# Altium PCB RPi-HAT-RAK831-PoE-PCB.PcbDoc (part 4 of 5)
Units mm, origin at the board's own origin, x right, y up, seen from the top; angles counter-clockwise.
Board outline 65 x 56 mm, 2 copper layers (Top Layer, Bottom Layer); 9 components, 14 nets, 9110 pads, 249 vias.
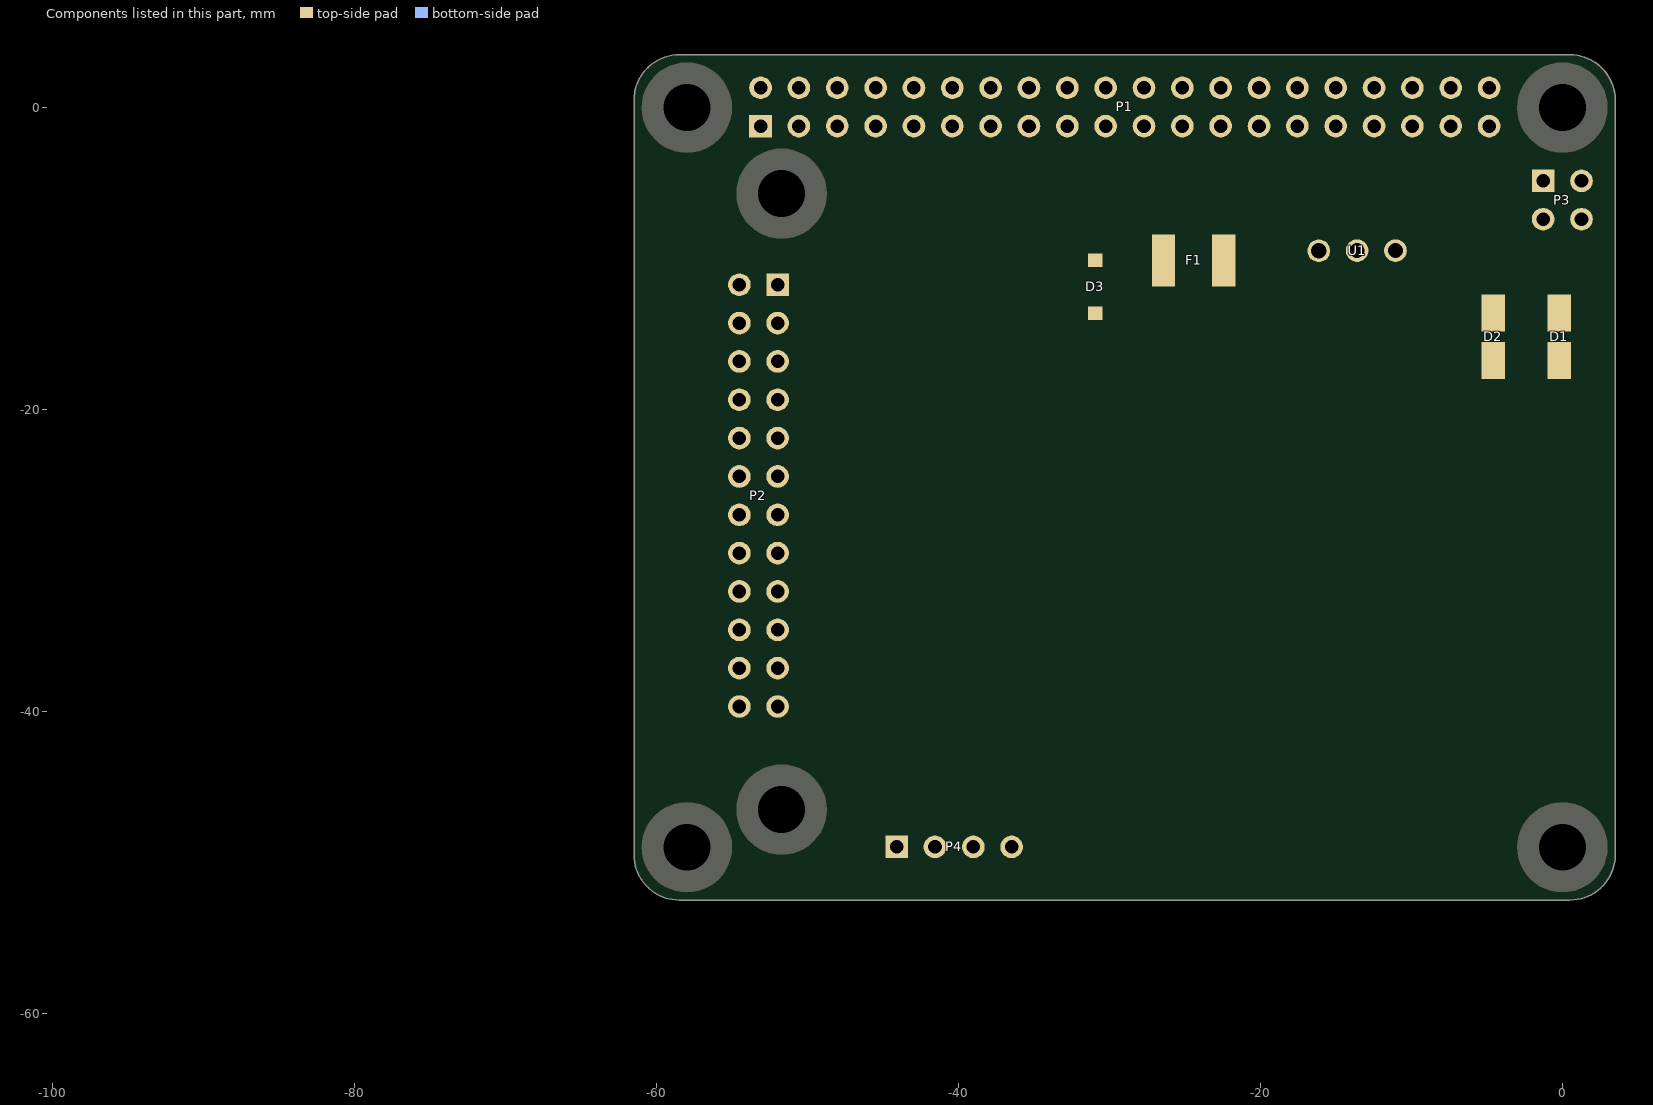
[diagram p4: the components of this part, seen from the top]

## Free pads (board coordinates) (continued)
  round 0.025 on Top Overlay: 1(-34.555,-45.483) 1(-34.555,-45.457) 1(-34.555,-45.432) 1(-34.555,-45.407) 1(-34.555,-45.381) 1(-34.555,-45.356) 1(-34.555,-45.33) 1(-34.555,-45.305) 1(-34.555,-45.28) 1(-34.555,-45.254) 1(-34.555,-45.229) 1(-34.555,-45.203) 1(-34.555,-45.178) 1(-34.555,-45.153) 1(-34.555,-45.127) 1(-34.555,-45.102) 1(-34.555,-45.076) 1(-34.555,-45.051) 1(-34.555,-45.026) 1(-34.555,-45) 1(-34.555,-44.975) 1(-34.555,-44.949) 1(-34.555,-44.924) 1(-34.555,-44.899) 1(-34.555,-44.873) 1(-34.555,-44.848) 1(-34.555,-44.822) 1(-34.555,-44.797) 1(-34.555,-44.772) 1(-34.555,-44.746) 1(-34.555,-44.721) 1(-34.555,-44.695) 1(-34.555,-44.67) 1(-34.555,-44.645) 1(-34.555,-44.619) 1(-34.555,-44.594) 1(-34.555,-44.568) 1(-34.555,-44.543) 1(-34.555,-44.518) 1(-34.555,-44.492) 1(-34.555,-44.467) 1(-34.555,-44.441) 1(-34.555,-44.416) 1(-34.555,-44.391) 1(-34.555,-44.365) 1(-34.555,-44.34) 1(-34.555,-44.314) 1(-34.555,-44.289) 1(-34.555,-44.264) 1(-34.555,-44.238) 1(-34.555,-44.213) 1(-34.555,-44.187) 1(-34.555,-44.162) 1(-34.555,-44.137) 1(-34.555,-44.111) 1(-34.555,-44.086) 1(-34.555,-44.06) 1(-34.555,-44.035) 1(-34.555,-44.01) 1(-34.555,-43.984) 1(-34.555,-43.959) 1(-34.555,-43.933) 1(-34.555,-43.908) 1(-34.555,-43.883) 1(-34.555,-43.857) 1(-34.555,-43.832) 1(-34.555,-43.806) 1(-34.555,-43.781) 1(-34.555,-43.756) 1(-34.555,-43.73) 1(-34.555,-43.705) 1(-34.555,-43.679) 1(-34.555,-43.654) 1(-34.555,-43.629) 1(-34.555,-43.603) 1(-34.555,-43.578) 1(-34.555,-43.552) 1(-34.555,-43.527) 1(-34.555,-43.502) 1(-34.555,-43.476) 1(-34.555,-43.451) 1(-34.555,-43.425) 1(-34.555,-43.4) 1(-34.555,-43.375) 1(-34.555,-43.349) 1(-34.555,-43.324) 1(-34.555,-43.298) 1(-34.555,-43.273) 1(-34.555,-43.248) 1(-34.555,-43.222) 1(-34.555,-43.197) 1(-34.555,-43.171) 1(-34.555,-43.146) 1(-34.53,-43.121) 1(-33.971,-44.975) 1(-33.971,-44.949) 1(-33.971,-44.924) 1(-33.971,-44.899) 1(-33.971,-44.873) 1(-33.971,-44.848) 1(-33.971,-44.822) 1(-33.971,-44.797) 1(-33.971,-44.772) 1(-33.971,-44.746) 1(-33.971,-44.721) 1(-33.971,-44.695) 1(-33.971,-44.67) 1(-33.971,-44.645) 1(-33.971,-44.619) 1(-33.971,-44.594) 1(-33.971,-44.568) 1(-33.971,-44.543) 1(-33.971,-44.518) 1(-33.971,-44.492) 1(-33.971,-44.467) 1(-33.971,-44.441) 1(-33.971,-44.416) 1(-33.971,-44.391) 1(-33.971,-44.365) 1(-33.971,-44.34) 1(-33.971,-44.314) 1(-33.971,-44.289) 1(-33.971,-44.264) 1(-33.971,-44.238) 1(-33.971,-44.213) 1(-33.971,-44.187) 1(-33.971,-44.162) 1(-33.971,-44.137) 1(-33.971,-44.111) 1(-33.971,-44.086) 1(-33.971,-44.06) 1(-33.971,-44.035) 1(-33.971,-44.01) 1(-33.971,-43.984) 1(-33.971,-43.959) 1(-33.971,-43.933) 1(-33.971,-43.908) 1(-33.971,-43.883) 1(-33.971,-43.857) 1(-33.971,-43.832) 1(-33.971,-43.806) 1(-33.971,-43.781) 1(-33.971,-43.756) 1(-33.971,-43.73) 1(-33.971,-43.705) 1(-33.971,-43.679) 1(-33.971,-43.654) 1(-33.971,-43.629) 1(-33.971,-43.603) 1(-33.971,-43.578) 1(-33.971,-43.552) 1(-33.971,-43.527) 1(-33.971,-43.502) 1(-33.971,-43.476) 1(-33.971,-43.451) 1(-33.971,-43.425) 1(-33.971,-43.4) 1(-33.971,-43.375) 1(-33.971,-43.349) 1(-33.971,-43.324) 1(-33.971,-43.298) 1(-33.971,-43.273) 1(-33.971,-43.248) 1(-33.971,-43.222) 1(-33.971,-43.197) 1(-33.971,-43.171) 1(-33.971,-43.146) 1(-33.971,-43.121) 1(-33.336,-46.753) 1(-33.336,-46.727) 1(-33.336,-46.702) 1(-33.336,-42.486) 1(-33.336,-42.46) 1(-33.336,-42.435) 1(-33.31,-46.778) 1(-33.31,-46.677) 1(-33.31,-42.536) 1(-33.31,-42.511) 1(-33.285,-46.804) 1(-33.285,-46.651) 1(-33.285,-42.562) 1(-33.285,-42.409) 1(-33.26,-46.626) 1(-33.26,-46.6) 1(-33.26,-42.613) 1(-33.26,-42.587) 1(-33.26,-42.384) 1(-33.234,-46.829) 1(-33.234,-46.575) 1(-33.234,-42.638) 1(-33.209,-46.55) 1(-33.209,-42.663) 1(-33.183,-46.854) 1(-33.183,-46.524) 1(-33.183,-42.689) 1(-33.183,-42.359) 1(-33.158,-46.88) 1(-33.158,-42.689) 1(-33.158,-42.333) 1(-33.133,-46.524) 1(-33.107,-46.55) 1(-33.107,-42.663) 1(-33.107,-42.308) 1(-33.082,-46.905) 1(-33.082,-42.638) 1(-33.056,-46.575) 1(-33.056,-42.282) 1(-33.031,-46.931) 1(-33.031,-46.27) 1(-33.031,-45.483) 1(-33.031,-45.457) 1(-33.031,-45.432) 1(-33.031,-45.407) 1(-33.031,-45.381) 1(-33.031,-45.356) 1(-33.031,-45.33) 1(-33.031,-45.305) 1(-33.031,-45.28) 1(-33.031,-45.254) 1(-33.031,-45.229) 1(-33.031,-45.203) 1(-33.031,-45.178) 1(-33.031,-45.153) 1(-33.031,-45.127) 1(-33.031,-45.102) 1(-33.031,-45.076) 1(-33.031,-45.051) 1(-33.031,-45.026) 1(-33.031,-45) 1(-33.031,-42.917) 1(-33.031,-42.613) 1(-33.006,-46.956) 1(-33.006,-46.6) 1(-33.006,-46.296) 1(-33.006,-46.245) 1(-33.006,-42.968) 1(-33.006,-42.943) 1(-33.006,-42.257) 1(-32.98,-46.626) 1(-32.98,-46.321) 1(-32.98,-46.219) 1(-32.98,-42.994) 1(-32.98,-42.892) 1(-32.98,-42.587) 1(-32.955,-46.346) 1(-32.955,-46.194) 1(-32.955,-46.169) 1(-32.955,-43.044) 1(-32.955,-43.019) 1(-32.955,-42.867) 1(-32.955,-42.232) 1(-32.929,-46.981) 1(-32.929,-46.143) 1(-32.929,-43.07) 1(-32.929,-42.562) 1(-32.904,-46.651) 1(-32.904,-46.118) 1(-32.904,-43.095) 1(-32.904,-42.841) 1(-32.879,-47.007) 1(-32.879,-46.372) 1(-32.879,-44.695) 1(-32.879,-44.67) 1(-32.879,-44.645) 1(-32.879,-44.619) 1(-32.879,-44.594) 1(-32.879,-44.568) 1(-32.879,-44.543) 1(-32.879,-44.518) 1(-32.879,-42.536) 1(-32.879,-42.206) 1(-32.853,-46.677) 1(-32.853,-46.397) 1(-32.853,-44.873) 1(-32.853,-44.848) 1(-32.853,-44.822) 1(-32.853,-44.797) 1(-32.853,-44.772) 1(-32.853,-44.746) 1(-32.853,-44.721) 1(-32.853,-44.492) 1(-32.853,-44.467) 1(-32.853,-44.441) 1(-32.853,-44.416) 1(-32.853,-44.391) 1(-32.853,-44.365) 1(-32.853,-43.095) 1(-32.853,-42.816) 1(-32.828,-46.118) 1(-32.828,-44.949) 1(-32.828,-44.924) 1(-32.828,-44.899) 1(-32.828,-44.34) 1(-32.828,-44.314) 1(-32.828,-44.289) 1(-32.828,-44.264) 1(-32.828,-42.511) 1(-32.802,-47.032) 1(-32.802,-46.702) 1(-32.802,-46.423) 1(-32.802,-46.143) 1(-32.802,-45.026) 1(-32.802,-45) 1(-32.802,-44.975) 1(-32.802,-44.238) 1(-32.802,-44.213) 1(-32.802,-44.187) 1(-32.802,-43.07) 1(-32.802,-42.79) 1(-32.802,-42.181) 1(-32.777,-45.076) 1(-32.777,-45.051) 1(-32.777,-44.162) 1(-32.777,-44.137) 1(-32.752,-46.169) 1(-32.752,-45.127) 1(-32.752,-45.102) 1(-32.752,-44.111) 1(-32.752,-44.086) 1(-32.752,-43.044) 1(-32.752,-42.765) 1(-32.752,-42.486) 1(-32.752,-42.155) 1(-32.726,-47.058) 1(-32.726,-46.727) 1(-32.726,-46.448) 1(-32.726,-45.178) 1(-32.726,-45.153) 1(-32.726,-44.06) 1(-32.726,-43.019) 1(-32.701,-46.194) 1(-32.701,-45.838) 1(-32.701,-45.813) 1(-32.701,-45.203) 1(-32.701,-44.035) 1(-32.701,-44.01) 1(-32.701,-43.4) 1(-32.701,-43.375) 1(-32.701,-42.74) 1(-32.675,-46.753) 1(-32.675,-46.473) 1(-32.675,-45.864) 1(-32.675,-45.788) 1(-32.675,-45.229) 1(-32.675,-43.984) 1(-32.675,-43.425) 1(-32.675,-43.349) 1(-32.675,-42.46) 1(-32.65,-47.083) 1(-32.65,-46.219) 1(-32.65,-45.889) 1(-32.65,-45.762) 1(-32.65,-45.737) 1(-32.65,-45.254) 1(-32.65,-43.959) 1(-32.65,-43.476) 1(-32.65,-43.451) 1(-32.65,-43.324) 1(-32.65,-42.994) 1(-32.65,-42.13) 1(-32.625,-46.499) 1(-32.625,-45.711) 1(-32.625,-45.28) 1(-32.625,-43.933) 1(-32.625,-43.502) 1(-32.625,-42.714) 1(-32.599,-46.778) 1(-32.599,-46.245) 1(-32.599,-45.305) 1(-32.599,-43.908) 1(-32.599,-43.298) 1(-32.599,-42.968) 1(-32.599,-42.435) 1(-32.574,-47.108) 1(-32.574,-45.915) 1(-32.574,-45.711) 1(-32.574,-45.33) 1(-32.574,-43.883) 1(-32.574,-43.502) 1(-32.574,-42.689) 1(-32.574,-42.105) 1(-32.548,-46.524) 1(-32.548,-45.356) 1(-32.548,-43.857) 1(-32.548,-43.273) 1(-32.523,-46.27) 1(-32.523,-45.94) 1(-32.523,-45.737) 1(-32.523,-43.476) 1(-32.523,-42.943) 1(-32.523,-42.409) 1(-32.498,-46.804) 1(-32.498,-45.381) 1(-32.498,-43.832) 1(-32.498,-43.248) 1(-32.472,-46.55) 1(-32.472,-45.965) 1(-32.472,-45.762) 1(-32.472,-45.407) 1(-32.472,-43.806) 1(-32.472,-43.451) 1(-32.472,-42.663) 1(-32.472,-42.079) 1(-32.447,-47.134) 1(-32.447,-46.296) 1(-32.447,-42.917) 1(-32.421,-46.829) 1(-32.421,-45.788) 1(-32.421,-45.432) 1(-32.421,-43.781) 1(-32.421,-43.425) 1(-32.421,-43.222) 1(-32.396,-46.575) 1(-32.396,-45.991) 1(-32.396,-42.384) 1(-32.371,-46.321) 1(-32.371,-45.457) 1(-32.371,-43.756) 1(-32.371,-43.4) 1(-32.371,-42.892) 1(-32.371,-42.638) 1(-32.345,-46.016) 1(-32.345,-45.813) 1(-32.345,-44.67) 1(-32.345,-44.645) 1(-32.345,-44.619) 1(-32.345,-44.594) 1(-32.345,-44.568) 1(-32.345,-44.543) 1(-32.32,-47.159) 1(-32.32,-45.483) 1(-32.32,-44.797) 1(-32.32,-44.772) 1(-32.32,-44.746) 1(-32.32,-44.721) 1(-32.32,-44.695) 1(-32.32,-44.518) 1(-32.32,-44.492) 1(-32.32,-44.467) 1(-32.32,-44.441) 1(-32.32,-44.416) 1(-32.32,-43.197) 1(-32.294,-46.854) 1(-32.294,-44.899) 1(-32.294,-44.873) 1(-32.294,-44.848) 1(-32.294,-44.822) 1(-32.294,-44.391) 1(-32.294,-44.365) 1(-32.294,-44.34) 1(-32.294,-44.314) 1(-32.294,-43.73) 1(-32.269,-45.838) 1(-32.269,-44.949) 1(-32.269,-44.924) 1(-32.269,-44.289) 1(-32.269,-43.375) 1(-32.269,-42.867) 1(-32.269,-42.359) 1(-32.269,-42.054) 1(-32.244,-46.6) 1(-32.244,-46.346) 1(-32.244,-46.042) 1(-32.244,-45.508) 1(-32.244,-44.975) 1(-32.244,-44.264) 1(-32.244,-44.238) 1(-32.244,-42.613) 1(-32.218,-45) 1(-32.218,-44.213) 1(-32.218,-43.705) 1(-32.218,-43.171) 1(-32.193,-45.864) 1(-32.193,-45.026) 1(-32.193,-44.187) 1(-32.167,-45.051) 1(-32.167,-44.162) 1(-32.142,-47.185) 1(-32.142,-45.076) 1(-32.142,-43.349) 1(-32.117,-44.137) 1(-32.117,-43.679) 1(-32.091,-46.372) 1(-32.091,-46.067) 1(-32.091,-45.534) 1(-32.091,-45.102) 1(-32.066,-44.111) 1(-32.066,-43.146) 1(-32.04,-46.88) 1(-32.04,-46.626) 1(-32.015,-42.333) 1(-31.99,-45.127) 1(-31.99,-44.086) 1(-31.913,-45.889) 1(-31.888,-45.889) 1(-31.863,-45.127) 1(-31.863,-44.086) 1(-31.863,-42.333) 1(-31.812,-43.146) 1(-31.786,-46.626) 1(-31.761,-46.88) 1(-31.761,-44.111) 1(-31.736,-46.067) 1(-31.736,-45.534) 1(-31.736,-45.102) 1(-31.736,-43.679) 1(-31.71,-46.372) 1(-31.71,-45.076) 1(-31.71,-44.137) 1(-31.71,-43.349) 1(-31.659,-47.185) 1(-31.659,-45.051) 1(-31.659,-44.187) 1(-31.659,-44.162) 1(-31.634,-45.864) 1(-31.634,-45.026) 1(-31.634,-44.213) 1(-31.634,-43.171) 1(-31.634,-42.613) 1(-31.609,-45.508) 1(-31.609,-45) 1(-31.609,-44.238) 1(-31.609,-43.705) 1(-31.609,-43.375) 1(-31.609,-42.867) 1(-31.609,-42.359) 1(-31.609,-42.054) 1(-31.583,-46.6) 1(-31.583,-44.975) 1(-31.583,-44.949) 1(-31.583,-44.289) 1(-31.583,-44.264) 1(-31.558,-46.346) 1(-31.558,-46.042) 1(-31.558,-44.924) 1(-31.558,-44.899) 1(-31.558,-44.873) 1(-31.558,-44.34) 1(-31.558,-44.314) 1(-31.532,-45.838) 1(-31.532,-45.483) 1(-31.532,-44.848) 1(-31.532,-44.822) 1(-31.532,-44.797) 1(-31.532,-44.416) 1(-31.532,-44.391) 1(-31.532,-44.365) 1(-31.532,-43.73) 1(-31.532,-43.197) 1(-31.507,-46.854) 1(-31.507,-44.772) 1(-31.507,-44.746) 1(-31.507,-44.721) 1(-31.507,-44.695) 1(-31.507,-44.67) 1(-31.507,-44.645) 1(-31.507,-44.619) 1(-31.507,-44.594) 1(-31.507,-44.568) 1(-31.507,-44.543) 1(-31.507,-44.518) 1(-31.507,-44.492) 1(-31.507,-44.467) 1(-31.507,-44.441) 1(-31.507,-43.4) 1(-31.507,-42.892) 1(-31.507,-42.638) 1(-31.482,-47.159) 1(-31.482,-42.384) 1(-31.456,-46.016) 1(-31.456,-45.813) 1(-31.456,-45.457) 1(-31.456,-43.756) 1(-31.456,-43.425) 1(-31.456,-43.222) 1(-31.431,-46.575) 1(-31.431,-46.321) 1(-31.431,-43.781) 1(-31.431,-42.917) 1(-31.405,-45.991) 1(-31.405,-45.432) 1(-31.405,-43.451) 1(-31.405,-42.663) 1(-31.405,-42.079) 1(-31.38,-46.829) 1(-31.38,-45.788) 1(-31.38,-45.407) 1(-31.38,-43.806) 1(-31.38,-43.248) 1(-31.355,-47.134) 1(-31.355,-46.296) 1(-31.355,-45.762) 1(-31.355,-42.409) 1(-31.329,-46.55) 1(-31.329,-45.965) 1(-31.329,-45.381) 1(-31.329,-43.832) 1(-31.329,-43.476) 1(-31.329,-43.273) 1(-31.329,-42.943) 1(-31.304,-46.804) 1(-31.304,-45.737) 1(-31.304,-45.356) 1(-31.304,-43.857) 1(-31.304,-43.502) 1(-31.304,-42.689) 1(-31.304,-42.105) 1(-31.278,-46.27) 1(-31.278,-45.94) 1(-31.278,-43.883) 1(-31.278,-43.298) 1(-31.278,-42.968) 1(-31.278,-42.435) 1(-31.253,-46.524) 1(-31.253,-45.711) 1(-31.253,-45.33) 1(-31.253,-43.527) 1(-31.253,-42.714) 1(-31.228,-47.108) 1(-31.228,-45.915) 1(-31.228,-45.711) 1(-31.228,-45.305) 1(-31.228,-43.933) 1(-31.228,-43.908) 1(-31.228,-43.527) 1(-31.228,-43.324) 1(-31.228,-42.994) 1(-31.228,-42.13) 1(-31.202,-46.778) 1(-31.202,-46.245) 1(-31.202,-45.737) 1(-31.202,-45.28) 1(-31.202,-43.959) 1(-31.202,-43.502) 1(-31.202,-43.476) 1(-31.202,-42.46) 1(-31.177,-46.499) 1(-31.177,-45.889) 1(-31.177,-45.788) 1(-31.177,-45.762) 1(-31.177,-45.254) 1(-31.177,-45.229) 1(-31.177,-43.451) 1(-31.177,-43.349) 1(-31.177,-42.74) 1(-31.151,-47.083) 1(-31.151,-46.219) 1(-31.151,-45.813) 1(-31.151,-45.203) 1(-31.151,-44.01) 1(-31.151,-43.984) 1(-31.151,-43.425) 1(-31.151,-43.4) 1(-31.151,-43.375) 1(-31.151,-43.019) 1(-31.126,-46.753) 1(-31.126,-46.473) 1(-31.126,-46.194) 1(-31.126,-45.864) 1(-31.126,-45.838) 1(-31.126,-45.178) 1(-31.126,-44.035) 1(-31.126,-42.486) 1(-31.126,-42.155) 1(-31.101,-45.153) 1(-31.101,-45.127) 1(-31.101,-44.086) 1(-31.101,-44.06) 1(-31.101,-43.044) 1(-31.101,-42.765) 1(-31.075,-47.058) 1(-31.075,-46.727) 1(-31.075,-46.448) 1(-31.075,-45.102) 1(-31.075,-45.076) 1(-31.075,-44.137) 1(-31.075,-44.111) 1(-31.075,-43.07) 1(-31.075,-42.79) 1(-31.05,-46.169) 1(-31.05,-45.051) 1(-31.05,-45.026) 1(-31.05,-44.187) 1(-31.05,-44.162) 1(-31.05,-42.511) 1(-31.05,-42.181) 1(-31.024,-46.143) 1(-31.024,-45) 1(-31.024,-44.975) 1(-31.024,-44.949) 1(-31.024,-44.264) 1(-31.024,-44.238) 1(-31.024,-44.213) 1(-31.024,-43.095) 1(-31.024,-42.816) 1(-30.999,-47.032) 1(-30.999,-46.702) 1(-30.999,-46.423) 1(-30.999,-44.924) 1(-30.999,-44.899) 1(-30.999,-44.873) 1(-30.999,-44.848) 1(-30.999,-44.822) 1(-30.999,-44.797) 1(-30.999,-44.416) 1(-30.999,-44.391) 1(-30.999,-44.365) 1(-30.999,-44.34) 1(-30.999,-44.314) 1(-30.999,-44.289) 1(-30.999,-42.536) 1(-30.999,-42.206) 1(-30.974,-46.397) 1(-30.974,-46.118) 1(-30.974,-44.772) 1(-30.974,-44.746) 1(-30.974,-44.721) 1(-30.974,-44.695) 1(-30.974,-44.67) 1(-30.974,-44.645) 1(-30.974,-44.619) 1(-30.974,-44.594) 1(-30.974,-44.568) 1(-30.974,-44.543) 1(-30.974,-44.518) 1(-30.974,-44.492) 1(-30.974,-44.467) 1(-30.974,-44.441) 1(-30.974,-43.121) 1(-30.948,-46.677) 1(-30.948,-43.121) 1(-30.948,-42.841) 1(-30.948,-42.562) 1(-30.923,-47.007) 1(-30.923,-46.372) 1(-30.923,-46.143) 1(-30.923,-46.118) 1(-30.923,-43.095) 1(-30.923,-42.867) 1(-30.923,-42.232) 1(-30.897,-46.651) 1(-30.897,-46.169) 1(-30.897,-43.07) 1(-30.897,-43.044) 1(-30.897,-42.587) 1(-30.872,-46.981) 1(-30.872,-46.346) 1(-30.872,-46.219) 1(-30.872,-46.194) 1(-30.872,-43.019) 1(-30.872,-42.892) 1(-30.872,-42.257) 1(-30.847,-46.626) 1(-30.847,-46.245) 1(-30.847,-42.994) 1(-30.847,-42.968) 1(-30.847,-42.917) 1(-30.847,-42.613) 1(-30.821,-46.956) 1(-30.821,-46.321) 1(-30.821,-46.296) 1(-30.821,-46.27) 1(-30.821,-42.943) 1(-30.821,-42.282) 1(-30.796,-46.6) 1(-30.796,-42.638) 1(-30.77,-46.931) 1(-30.77,-42.308) 1(-30.745,-46.575) 1(-30.745,-42.663) 1(-30.72,-46.905) 1(-30.72,-42.689) 1(-30.72,-42.333) 1(-30.694,-46.55) 1(-30.669,-46.88) 1(-30.669,-46.524) 1(-30.669,-42.714) 1(-30.669,-42.359) 1(-30.643,-46.55) 1(-30.643,-46.524) 1(-30.643,-45.483) 1(-30.643,-45.457) 1(-30.643,-45.432) 1(-30.643,-45.407) 1(-30.643,-45.381) 1(-30.643,-45.356) 1(-30.643,-45.33) 1(-30.643,-45.305) 1(-30.643,-45.28) 1(-30.643,-45.254) 1(-30.643,-45.229) 1(-30.643,-45.203) 1(-30.643,-45.178) 1(-30.643,-45.153) 1(-30.643,-45.127) 1(-30.643,-45.102) 1(-30.643,-45.076) 1(-30.643,-45.051) 1(-30.643,-45.026) 1(-30.643,-45) 1(-30.643,-44.975) 1(-30.643,-44.949) 1(-30.643,-44.924) 1(-30.643,-44.899) 1(-30.643,-44.873) 1(-30.643,-44.848) 1(-30.643,-44.822) 1(-30.643,-44.797) 1(-30.643,-44.772) 1(-30.643,-44.746) 1(-30.643,-44.721) 1(-30.643,-44.695) 1(-30.643,-44.67) 1(-30.643,-44.645) 1(-30.643,-44.619) 1(-30.643,-44.594) 1(-30.643,-44.568) 1(-30.643,-44.543) 1(-30.643,-44.518) 1(-30.643,-44.492) 1(-30.643,-44.467) 1(-30.643,-44.441) 1(-30.643,-44.416) 1(-30.643,-44.391) 1(-30.643,-44.365) 1(-30.643,-44.34) 1(-30.643,-44.314) 1(-30.643,-44.289) 1(-30.643,-44.264) 1(-30.643,-44.238) 1(-30.643,-44.213) 1(-30.643,-44.187) 1(-30.643,-44.162) 1(-30.643,-44.137) 1(-30.643,-44.111) 1(-30.643,-44.086) 1(-30.643,-44.06) 1(-30.643,-44.035) 1(-30.643,-44.01) 1(-30.643,-43.984) 1(-30.643,-43.959) 1(-30.643,-43.933) 1(-30.643,-43.908) 1(-30.643,-43.883) 1(-30.643,-43.857) 1(-30.643,-43.832) 1(-30.643,-43.806) 1(-30.643,-43.781) 1(-30.643,-43.756) 1(-30.643,-43.73) 1(-30.643,-43.705) 1(-30.643,-43.679) 1(-30.643,-43.654) 1(-30.643,-43.629) 1(-30.643,-43.603) 1(-30.643,-43.578) 1(-30.643,-43.552) 1(-30.643,-43.527) 1(-30.643,-43.502) 1(-30.643,-43.476) 1(-30.643,-43.451) 1(-30.643,-43.425) 1(-30.643,-43.4) 1(-30.643,-43.375) 1(-30.643,-43.349) 1(-30.643,-43.324) 1(-30.643,-43.298) 1(-30.643,-43.273) 1(-30.643,-43.248) 1(-30.643,-43.222) 1(-30.643,-43.197) 1(-30.643,-43.171) 1(-30.643,-43.146) 1(-30.643,-43.121) 1(-30.643,-42.714) 1(-30.643,-42.689) 1(-30.618,-46.854) 1(-30.618,-46.575) 1(-30.618,-42.663) 1(-30.618,-42.384) 1(-30.593,-46.829) 1(-30.593,-46.626) 1(-30.593,-46.6) 1(-30.593,-42.638) 1(-30.593,-42.409) 1(-30.567,-46.651) 1(-30.567,-42.613) 1(-30.567,-42.587) 1(-30.542,-46.804) 1(-30.542,-46.702) 1(-30.542,-46.677) 1(-30.542,-42.562) 1(-30.542,-42.435) 1(-30.516,-46.727) 1(-30.516,-42.536) 1(-30.516,-42.511) 1(-30.491,-46.778) 1(-30.491,-46.753) 1(-30.491,-42.486) 1(-30.491,-42.46) 1(-30.034,-45.483) 1(-30.034,-45.457) 1(-30.034,-45.432) 1(-30.034,-45.407) 1(-30.034,-45.381) 1(-30.034,-45.356) 1(-30.034,-45.33) 1(-30.034,-45.305) 1(-30.034,-45.28) 1(-30.034,-45.254) 1(-30.034,-45.229) 1(-30.034,-45.203) 1(-30.034,-45.178) 1(-30.034,-45.153) 1(-30.034,-45.127) 1(-30.034,-45.102) 1(-30.034,-45.076) 1(-30.034,-45.051) 1(-30.034,-45.026) 1(-30.034,-45) 1(-30.034,-44.975) 1(-30.034,-44.949) 1(-30.034,-44.924) 1(-30.034,-44.899) 1(-30.034,-44.873) 1(-30.034,-44.848) 1(-30.034,-44.822) 1(-30.034,-44.797) 1(-30.034,-44.772) 1(-30.034,-44.746) 1(-30.034,-44.721) 1(-30.034,-44.695) 1(-30.034,-44.67) 1(-30.034,-44.187) 1(-30.034,-44.162) 1(-30.034,-44.137) 1(-30.034,-44.111) 1(-30.034,-44.086) 1(-30.034,-44.06) 1(-30.034,-44.035) 1(-30.034,-44.01) 1(-30.034,-43.984) 1(-30.034,-43.959) 1(-30.034,-43.933) 1(-30.034,-43.908) 1(-30.034,-43.883) 1(-30.034,-43.857) 1(-30.034,-43.832) 1(-30.034,-43.806) 1(-30.034,-43.781) 1(-30.034,-43.756) 1(-30.034,-43.73) 1(-30.034,-43.705) 1(-30.034,-43.679) 1(-30.034,-43.654) 1(-30.034,-43.629) 1(-30.034,-43.603) 1(-30.034,-43.578) 1(-29.678,-44.67) 1(-29.653,-44.695) 1(-29.627,-44.746) 1(-29.627,-44.721) 1(-29.602,-44.797) 1(-29.602,-44.772) 1(-29.577,-44.822) 1(-29.551,-44.873) 1(-29.551,-44.848) 1(-29.526,-44.924) 1(-29.526,-44.899) 1(-29.5,-44.975) 1(-29.5,-44.949) 1(-29.475,-45.026) 1(-29.475,-45) 1(-29.45,-45.076) 1(-29.45,-45.051) 1(-29.45,-43.578) 1(-29.424,-45.127) 1(-29.424,-45.102) 1(-29.424,-43.121) 1(-29.399,-45.153) 1(-29.399,-44.187) 1(-29.373,-45.203) 1(-29.373,-45.178) 1(-29.348,-45.254) 1(-29.348,-45.229) 1(-29.348,-44.162) 1(-29.348,-43.603) 1(-29.323,-45.305) 1(-29.323,-45.28) 1(-29.297,-45.356) 1(-29.297,-45.33) 1(-29.297,-44.137) 1(-29.297,-43.629) 1(-29.272,-45.381) 1(-29.272,-44.111) 1(-29.272,-43.654) 1(-29.246,-45.432) 1(-29.246,-45.407) 1(-29.246,-44.086) 1(-29.246,-43.679) 1(-29.221,-45.483) 1(-29.221,-45.457) 1(-29.221,-44.06) 1(-29.221,-44.035) 1(-29.221,-44.01) 1(-29.221,-43.756) 1(-29.221,-43.73) 1(-29.221,-43.705) 1(-29.196,-43.984) 1(-29.196,-43.959) 1(-29.196,-43.933) 1(-29.196,-43.908) 1(-29.196,-43.883) 1(-29.196,-43.857) 1(-29.196,-43.832) 1(-29.196,-43.806) 1(-29.196,-43.781) 1(-29.145,-43.146) 1(-29.043,-44.594) 1(-29.043,-44.568) 1(-29.043,-44.543) 1(-29.043,-43.171) 1(-29.018,-44.645) 1(-29.018,-44.619) 1(-28.992,-44.695) 1(-28.992,-44.67) 1(-28.992,-43.197) 1(-28.967,-44.721) 1(-28.967,-44.518) 1(-28.942,-44.772) 1(-28.942,-44.746) 1(-28.942,-44.492) 1(-28.942,-43.222) 1(-28.916,-44.822) 1(-28.916,-44.797) 1(-28.891,-44.873) 1(-28.891,-44.848) 1(-28.891,-44.467) 1(-28.891,-43.248) 1(-28.865,-44.924) 1(-28.865,-44.899) 1(-28.865,-43.273) 1(-28.84,-44.949) 1(-28.84,-44.441) 1(-28.815,-45) 1(-28.815,-44.975) 1(-28.815,-44.416) 1(-28.815,-43.298) 1(-28.789,-45.051) 1(-28.789,-45.026) 1(-28.789,-44.391) 1(-28.789,-43.324) 1(-28.764,-45.102) 1(-28.764,-45.076) 1(-28.764,-44.365) 1(-28.764,-43.349) 1(-28.738,-45.127) 1(-28.738,-44.34) 1(-28.738,-43.375) 1(-28.713,-45.178) 1(-28.713,-45.153) 1(-28.713,-44.314) 1(-28.713,-44.289) 1(-28.713,-43.425) 1(-28.713,-43.4) 1(-28.688,-45.229) 1(-28.688,-45.203) 1(-28.688,-44.264) 1(-28.688,-43.476) 1(-28.688,-43.451) 1(-28.662,-45.254) 1(-28.662,-44.238) 1(-28.662,-44.213) 1(-28.662,-43.502) 1(-28.637,-45.305) 1(-28.637,-45.28) 1(-28.637,-44.187) 1(-28.637,-44.162) 1(-28.637,-44.137) 1(-28.637,-43.603) 1(-28.637,-43.578) 1(-28.637,-43.552) 1(-28.637,-43.527) 1(-28.611,-45.356) 1(-28.611,-45.33) 1(-28.611,-44.111) 1(-28.611,-44.086) 1(-28.611,-44.06) 1(-28.611,-43.705) 1(-28.611,-43.679) 1(-28.611,-43.654) 1(-28.611,-43.629) 1(-28.586,-45.407) 1(-28.586,-45.381) 1(-28.586,-44.035) 1(-28.586,-44.01) 1(-28.586,-43.984) 1(-28.586,-43.959) 1(-28.586,-43.933) 1(-28.586,-43.908) 1(-28.586,-43.883) 1(-28.586,-43.857) 1(-28.586,-43.832) 1(-28.586,-43.806) 1(-28.586,-43.781) 1(-28.586,-43.756) 1(-28.586,-43.73) 1(-28.561,-45.457) 1(-28.561,-45.432) 1(-28.535,-45.483) 1(-28.357,-45.153) 1(-28.357,-45.127) 1(-28.357,-45.102) 1(-28.357,-45.076) 1(-28.357,-45.051) 1(-28.357,-45.026) 1(-28.357,-45) 1(-28.357,-44.975) 1(-28.357,-44.949) 1(-28.357,-44.924) 1(-28.357,-44.899) 1(-28.357,-44.873) 1(-28.332,-45.229) 1(-28.332,-45.203) 1(-28.332,-45.178) 1(-28.332,-44.848) 1(-28.332,-44.822) 1(-28.332,-44.797) 1(-28.307,-45.28) 1(-28.307,-45.254) 1(-28.307,-44.772) 1(-28.307,-44.746) 1(-28.281,-45.33) 1(-28.281,-45.305) 1(-28.281,-44.721) 1(-28.281,-44.695) 1(-28.281,-44.238) 1(-28.281,-44.213) 1(-28.281,-44.187) 1(-28.281,-44.162) 1(-28.281,-44.137) 1(-28.281,-44.111) 1(-28.256,-45.356) 1(-28.256,-44.67) 1(-28.256,-44.086) 1(-28.256,-44.06) 1(-28.256,-44.035) 1(-28.23,-45.381) 1(-28.23,-44.645) 1(-28.23,-44.01) 1(-28.23,-43.984) 1(-28.23,-43.959) 1(-28.205,-45.407) 1(-28.205,-44.619) 1(-28.205,-43.933) 1(-28.18,-45.432) 1(-28.18,-44.594) 1(-28.18,-43.908) 1(-28.154,-44.568) 1(-28.154,-43.883) 1(-28.154,-43.857) 1(-28.129,-45.457) 1(-28.129,-43.832) 1(-28.103,-44.543) 1(-28.078,-45.483) 1(-28.078,-44.518) 1(-28.078,-43.806) 1(-28.053,-43.781) 1(-28.027,-45.508) 1(-28.002,-44.492) 1(-28.002,-43.756) 1(-27.951,-44.467) 1(-27.951,-43.73) 1(-27.926,-45.534) 1(-27.9,-44.441) 1(-27.875,-43.705) 1(-27.849,-45.026) 1(-27.849,-45) 1(-27.849,-44.975) 1(-27.849,-44.949) 1(-27.849,-44.924) 1(-27.824,-45.051) 1(-27.824,-44.899) 1(-27.824,-44.873) 1(-27.799,-45.102) 1(-27.799,-45.076) 1(-27.799,-44.848) 1(-27.773,-44.822) 1(-27.773,-44.416) 1(-27.773,-44.238) 1(-27.773,-44.213) 1(-27.748,-45.127) 1(-27.748,-44.797) 1(-27.748,-44.187) 1(-27.748,-44.162) 1(-27.748,-44.137) 1(-27.748,-43.679) 1(-27.722,-44.111) 1(-27.722,-44.086) 1(-27.697,-44.772) 1(-27.697,-44.391) 1(-27.672,-44.06) 1(-27.646,-44.035) 1(-27.621,-45.534) 1(-27.621,-44.746) 1(-27.57,-44.365) 1(-27.57,-44.01) 1(-27.545,-44.721) 1(-27.519,-45.508) 1(-27.494,-45.127) 1(-27.443,-45.483) 1(-27.443,-44.695) 1(-27.443,-44.01) 1(-27.418,-45.102) 1(-27.392,-45.457) 1(-27.392,-45.076) 1(-27.367,-45.051) 1(-27.367,-44.34) 1(-27.367,-44.035) 1(-27.341,-45.432) 1(-27.341,-45.026) 1(-27.341,-44.67) 1(-27.316,-45.407) 1(-27.316,-45) 1(-27.316,-44.975) 1(-27.316,-44.949) 1(-27.316,-44.06) 1(-27.291,-45.381) 1(-27.291,-44.924) 1(-27.291,-44.899) 1(-27.291,-44.873) 1(-27.291,-44.111) 1(-27.291,-44.086) 1(-27.291,-43.679) 1(-27.265,-45.356) 1(-27.265,-44.848) 1(-27.265,-44.822) 1(-27.265,-44.797) 1(-27.265,-44.772) 1(-27.265,-44.746) 1(-27.265,-44.721) 1(-27.265,-44.695) 1(-27.265,-44.67) 1(-27.265,-44.314) 1(-27.265,-44.289) 1(-27.265,-44.264) 1(-27.265,-44.238) 1(-27.265,-44.213) 1(-27.265,-44.187) 1(-27.265,-44.162) 1(-27.265,-44.137) 1(-27.24,-45.381) 1(-27.24,-45.356) 1(-27.214,-45.483) 1(-27.214,-45.457) 1(-27.214,-45.432) 1(-27.214,-45.407) 1(-27.164,-43.705) 1(-27.087,-43.73) 1(-27.011,-43.756) 1(-26.96,-43.781) 1(-26.935,-43.806) 1(-26.884,-43.832) 1(-26.859,-43.857) 1(-26.833,-43.908) 1(-26.833,-43.883) 1(-26.808,-43.959) 1(-26.808,-43.933) 1(-26.783,-44.035) 1(-26.783,-44.01) 1(-26.783,-43.984) 1(-26.783,-43.679) 1(-26.783,-43.654) 1(-26.757,-45.28) 1(-26.757,-45.254) 1(-26.757,-45.229) 1(-26.757,-45.203) 1(-26.757,-45.178) 1(-26.757,-45.153) 1(-26.757,-45.127) 1(-26.757,-45.102) 1(-26.757,-45.076) 1(-26.757,-45.051) 1(-26.757,-45.026) 1(-26.757,-45) 1(-26.757,-44.975) 1(-26.757,-44.949) 1(-26.757,-44.924) 1(-26.757,-44.899) 1(-26.757,-44.873) 1(-26.757,-44.848) 1(-26.757,-44.822) 1(-26.757,-44.797) 1(-26.757,-44.772) 1(-26.757,-44.746) 1(-26.757,-44.721) 1(-26.757,-44.695) 1(-26.757,-44.67) 1(-26.757,-44.645) 1(-26.757,-44.619) 1(-26.757,-44.594) 1(-26.757,-44.568) 1(-26.757,-44.543) 1(-26.757,-44.518) 1(-26.757,-44.492) 1(-26.757,-44.467) 1(-26.757,-44.441) 1(-26.757,-44.416) 1(-26.757,-44.391) 1(-26.757,-44.365) 1(-26.757,-44.34) 1(-26.757,-44.314) 1(-26.757,-44.289) 1(-26.757,-44.264) 1(-26.757,-44.238) 1(-26.757,-44.213) 1(-26.757,-44.187) 1(-26.757,-44.162) 1(-26.757,-44.137) 1(-26.757,-44.111) 1(-26.757,-44.086) 1(-26.757,-44.06) 1(-26.732,-45.457) 1(-26.732,-45.432) 1(-26.732,-45.407) 1(-26.732,-45.381) 1(-26.732,-45.356) 1(-26.732,-45.33) 1(-26.732,-45.305) 1(-26.706,-45.483) 1(-26.706,-43.959) 1(-26.706,-43.933) 1(-26.706,-43.908) 1(-26.706,-43.883) 1(-26.706,-43.857) 1(-26.706,-43.832) 1(-26.706,-43.806) 1(-26.706,-43.781) 1(-26.706,-43.756) 1(-26.706,-43.73) 1(-26.706,-43.705) 1(-26.63,-43.959) 1(-26.63,-43.933) 1(-26.63,-43.908) 1(-26.63,-43.883) 1(-26.63,-43.857) 1(-26.63,-43.832) 1(-26.63,-43.806) 1(-26.63,-43.781) 1(-26.63,-43.756) 1(-26.63,-43.73) 1(-26.63,-43.705) 1(-26.529,-43.679) 1(-26.529,-43.654) 1(-26.503,-43.959) 1(-26.503,-43.933) 1(-26.503,-43.908) 1(-26.503,-43.883) 1(-26.503,-43.857) 1(-26.503,-43.832) 1(-26.503,-43.806) 1(-26.503,-43.781) 1(-26.503,-43.756) 1(-26.503,-43.73) 1(-26.503,-43.705) 1(-26.503,-43.679) 1(-26.503,-43.654) 1(-26.452,-43.959) 1(-26.452,-43.933) 1(-26.452,-43.908) 1(-26.452,-43.883) 1(-26.452,-43.857) 1(-26.452,-43.832) 1(-26.452,-43.806) 1(-26.452,-43.781) 1(-26.427,-43.832) 1(-26.427,-43.806) 1(-26.427,-43.781) 1(-26.427,-43.679) 1(-26.427,-43.654) 1(-26.402,-43.908) 1(-26.402,-43.883) 1(-26.402,-43.857) 1(-26.402,-43.756) 1(-26.402,-43.73) 1(-26.402,-43.705) 1(-26.376,-43.959) 1(-26.376,-43.933) 1(-26.376,-43.806) 1(-26.376,-43.781) 1(-26.351,-43.857) 1(-26.351,-43.832) 1(-26.325,-43.959) 1(-26.325,-43.857) 1(-26.325,-43.832) 1(-26.325,-43.806) 1(-26.3,-43.933) 1(-26.3,-43.908) 1(-26.3,-43.781) 1(-26.3,-43.756) 1(-26.275,-43.883) 1(-26.275,-43.857) 1(-26.275,-43.832) 1(-26.275,-43.806) 1(-26.275,-43.73) 1(-26.275,-43.705) 1(-26.275,-43.679) 1(-26.249,-43.959) 1(-26.249,-43.933) 1(-26.249,-43.908) 1(-26.249,-43.883) 1(-26.249,-43.857) 1(-26.249,-43.832) 1(-26.249,-43.806) 1(-26.249,-43.654) 1(-26.198,-43.959) 1(-26.198,-43.933) 1(-26.198,-43.908) 1(-26.198,-43.883) 1(-26.198,-43.857) 1(-26.198,-43.832) 1(-26.198,-43.806) 1(-26.198,-43.781) 1(-26.198,-43.756) 1(-26.198,-43.73) 1(-26.198,-43.705) 1(-26.198,-43.679) 1(-26.198,-43.654) 1(-25.364,-44.825) 1(-25.364,-44.799) 1(-25.364,-44.774) 1(-25.364,-44.748) 1(-25.364,-44.723) 1(-25.364,-44.698) 1(-25.364,-44.672) 1(-25.364,-44.647) 1(-25.364,-44.621) 1(-25.364,-44.596) 1(-25.364,-44.571) 1(-25.364,-44.545) 1(-25.364,-44.52) 1(-25.364,-44.494) 1(-25.339,-45.053) 1(-25.339,-45.028) 1(-25.339,-45.002) 1(-25.339,-44.977) 1(-25.339,-44.952) 1(-25.339,-44.926) 1(-25.339,-44.901) 1(-25.339,-44.875) 1(-25.339,-44.85) 1(-25.339,-44.469) 1(-25.339,-44.444) 1(-25.339,-44.418) 1(-25.339,-44.393) 1(-25.339,-44.367) 1(-25.339,-44.342) 1(-25.339,-44.317) 1(-25.339,-44.291) 1(-25.339,-44.266) 1(-25.314,-45.18) 1(-25.314,-45.155) 1(-25.314,-45.129) 1(-25.314,-45.104) 1(-25.314,-45.079) 1(-25.314,-44.24) 1(-25.314,-44.215) 1(-25.314,-44.19) 1(-25.314,-44.164) 1(-25.314,-44.139) 1(-25.288,-45.282) 1(-25.288,-45.256) 1(-25.288,-45.231) 1(-25.288,-45.206) 1(-25.288,-44.113) 1(-25.288,-44.088) 1(-25.288,-44.063) 1(-25.288,-44.037) 1(-25.263,-45.358) 1(-25.263,-45.333) 1(-25.263,-45.307) 1(-25.263,-44.012) 1(-25.263,-43.986) 1(-25.263,-43.961) 1(-25.237,-45.434) 1(-25.237,-45.409) 1(-25.237,-45.383) 1(-25.237,-43.936) 1(-25.237,-43.91) 1(-25.237,-43.885) 1(-25.212,-45.51) 1(-25.212,-45.485) 1(-25.212,-45.46) 1(-25.212,-43.859) 1(-25.212,-43.834) 1(-25.212,-43.809) 1(-25.187,-45.561) 1(-25.187,-45.536) 1(-25.187,-43.783) 1(-25.187,-43.758) 1(-25.161,-45.612) 1(-25.161,-45.587) 1(-25.161,-43.732) 1(-25.161,-43.707) 1(-25.136,-45.663) 1(-25.136,-45.637) 1(-25.136,-43.682) 1(-25.136,-43.656) 1(-25.11,-45.688) 1(-25.11,-43.631) 1(-25.11,-43.605) 1(-25.085,-45.739) 1(-25.085,-45.714) 1(-25.085,-43.58) 1(-25.06,-45.79) 1(-25.06,-45.764) 1(-25.06,-43.555) 1(-25.06,-43.529) 1(-25.034,-45.815) 1(-25.034,-43.504) 1(-25.009,-45.841) 1(-25.009,-43.478) 1(-25.009,-43.453) 1(-24.983,-45.891) 1(-24.983,-45.866) 1(-24.983,-43.428) 1(-24.958,-45.917) 1(-24.958,-43.402) 1(-24.933,-45.942) 1(-24.933,-43.377) 1(-24.933,-43.351) 1(-24.907,-45.968) 1(-24.907,-43.326) 1(-24.882,-45.993) 1(-24.882,-43.301) 1(-24.856,-46.018) 1(-24.856,-43.275) 1(-24.831,-46.044) 1(-24.831,-43.25) 1(-24.806,-46.069) 1(-24.806,-43.224) 1(-24.78,-46.095) 1(-24.78,-43.199) 1(-24.755,-46.12) 1(-24.755,-43.174) 1(-24.729,-46.145) 1(-24.729,-43.148) 1(-24.704,-46.171) 1(-24.704,-43.123) 1(-24.679,-43.097) 1(-24.653,-46.196) 1(-24.628,-46.222) 1(-24.628,-43.072) 1(-24.602,-43.047) 1(-24.577,-46.247) 1(-24.577,-43.021) 1(-24.552,-46.272) 1(-24.526,-42.996) 1(-24.501,-46.298) 1(-24.501,-42.97) 1(-24.45,-46.323) 1(-24.45,-44.901) 1(-24.45,-44.875) 1(-24.45,-44.85) 1(-24.45,-44.825) 1(-24.45,-44.799) 1(-24.45,-44.774) 1(-24.45,-44.748) 1(-24.45,-44.723) 1(-24.45,-44.698) 1(-24.45,-44.672) 1(-24.45,-44.647) 1(-24.45,-44.621) 1(-24.45,-44.596) 1(-24.45,-44.571) 1(-24.45,-44.545) 1(-24.45,-44.52) 1(-24.45,-44.494) 1(-24.45,-44.469) 1(-24.45,-44.444) 1(-24.45,-44.418) 1(-24.45,-44.393) 1(-24.45,-44.367) 1(-24.45,-44.342) 1(-24.45,-42.945) 1(-24.425,-45.028) 1(-24.425,-45.002) 1(-24.425,-44.977) 1(-24.425,-44.952) 1(-24.425,-44.926) 1(-24.425,-44.317) 1(-24.425,-44.291) 1(-24.425,-44.266) 1(-24.425,-44.24) 1(-24.425,-44.215) 1(-24.425,-42.92) 1(-24.399,-46.349) 1(-24.399,-45.129) 1(-24.399,-45.104) 1(-24.399,-45.079) 1(-24.399,-45.053) 1(-24.399,-44.19) 1(-24.399,-44.164) 1(-24.399,-44.139) 1(-24.374,-45.18) 1(-24.374,-45.155) 1(-24.374,-44.113) 1(-24.374,-44.088) 1(-24.374,-44.063) 1(-24.374,-42.894) 1(-24.348,-46.374) 1(-24.348,-45.256) 1(-24.348,-45.231) 1(-24.348,-45.206) 1(-24.348,-44.037) 1(-24.348,-44.012) 1(-24.323,-45.307) 1(-24.323,-45.282) 1(-24.323,-43.986) 1(-24.323,-43.961) 1(-24.323,-42.869) 1(-24.298,-46.399) 1(-24.298,-45.358) 1(-24.298,-45.333) 1(-24.298,-43.936) 1(-24.298,-43.91) 1(-24.272,-45.383) 1(-24.272,-43.885) 1(-24.272,-43.859) 1(-24.272,-42.843) 1(-24.247,-45.434) 1(-24.247,-45.409) 1(-24.247,-43.834) 1(-24.221,-46.425) 1(-24.221,-45.46) 1(-24.221,-43.809) 1(-24.221,-43.783) 1(-24.221,-42.818) 1(-24.196,-45.485) 1(-24.196,-43.758) 1(-24.171,-46.45) 1(-24.171,-45.51) 1(-24.171,-43.732) 1(-24.171,-42.793) 1(-24.145,-45.536) 1(-24.145,-43.707) 1(-24.12,-45.561) 1(-24.12,-43.682) 1(-24.094,-45.587) 1(-24.094,-43.656) 1(-24.094,-42.767) 1(-24.069,-46.476) 1(-24.069,-45.612) 1(-24.069,-43.631) 1(-24.044,-45.637) 1(-24.044,-43.605) 1(-24.018,-45.663) 1(-24.018,-43.58) 1(-24.018,-42.742) 1(-23.993,-45.688) 1(-23.993,-43.555) 1(-23.967,-46.501) 1(-23.942,-45.714) 1(-23.942,-43.529) 1(-23.942,-42.716) 1(-23.917,-43.504) 1(-23.891,-45.739) 1(-23.866,-43.478) 1(-23.84,-46.526) 1(-23.84,-45.764) 1(-23.84,-42.691) 1(-23.815,-43.453) 1(-23.79,-45.79) 1(-23.764,-43.428) 1(-23.713,-45.815) 1(-23.713,-43.402) 1(-23.713,-42.666) 1(-23.663,-46.552) 1(-23.637,-45.841) 1(-23.637,-43.377) 1(-23.586,-45.028) 1(-23.586,-45.002) 1(-23.586,-44.977) 1(-23.586,-44.952) 1(-23.586,-44.926) 1(-23.586,-44.901) 1(-23.586,-44.875) 1(-23.586,-44.85) 1(-23.586,-44.825) 1(-23.586,-44.799) 1(-23.586,-44.774) 1(-23.586,-44.748) 1(-23.586,-44.723) 1(-23.586,-44.698) 1(-23.586,-44.672) 1(-23.586,-44.647) 1(-23.586,-44.621) 1(-23.586,-44.596) 1(-23.586,-44.571) 1(-23.586,-44.545) 1(-23.586,-44.52) 1(-23.586,-44.494) 1(-23.586,-44.469) 1(-23.586,-44.444) 1(-23.586,-44.418) 1(-23.586,-44.393) 1(-23.586,-44.367) 1(-23.561,-43.351) 1(-23.51,-45.866) 1(-23.51,-42.64) 1(-23.409,-43.326) 1(-23.129,-45.866) 1(-23.028,-46.552) 1(-22.977,-45.841) 1(-22.977,-43.326) 1(-22.901,-45.815) 1(-22.875,-42.64) 1(-22.85,-45.79) 1(-22.824,-45.764) 1(-22.824,-45.739) 1(-22.824,-45.714) 1(-22.824,-45.688) 1(-22.824,-45.663) 1(-22.824,-45.637) 1(-22.824,-45.612) 1(-22.824,-45.587) 1(-22.824,-45.561) 1(-22.824,-45.536) 1(-22.824,-45.51) 1(-22.824,-45.485) 1(-22.824,-45.46) 1(-22.824,-45.434) 1(-22.824,-45.409) 1(-22.824,-45.383) 1(-22.824,-45.358) 1(-22.824,-45.333) 1(-22.824,-45.307) 1(-22.824,-45.282) 1(-22.824,-45.256) 1(-22.824,-45.231) 1(-22.824,-45.206) 1(-22.824,-45.18) 1(-22.824,-45.155) 1(-22.824,-45.129) 1(-22.824,-45.104) 1(-22.824,-45.079) 1(-22.824,-45.053) 1(-22.799,-46.526) 1(-22.774,-43.351) 1(-22.647,-46.501) 1(-22.647,-43.377) 1(-22.647,-42.666) 1(-22.57,-43.402) 1(-22.545,-46.476) 1(-22.52,-42.691) 1(-22.469,-43.428) 1(-22.443,-46.45) 1(-22.393,-43.453) 1(-22.393,-42.716) 1(-22.367,-46.425) 1(-22.342,-43.478) 1(-22.291,-46.399) 1(-22.291,-43.504) 1(-22.291,-42.742) 1(-22.24,-43.529) 1(-22.215,-46.374) 1(-22.215,-42.767) 1(-22.189,-43.555) 1(-22.164,-46.349) 1(-22.139,-42.793) 1(-22.113,-46.323) 1(-22.113,-43.555) 1(-22.113,-43.529) 1(-22.113,-43.504) 1(-22.113,-43.478) 1(-22.113,-43.453) 1(-22.113,-43.428) 1(-22.113,-43.402) 1(-22.113,-43.377) 1(-22.113,-43.351) 1(-22.113,-43.326) 1(-22.113,-43.301) 1(-22.113,-43.275) 1(-22.113,-43.25) 1(-22.113,-43.224) 1(-22.113,-43.199) 1(-22.113,-43.174) 1(-22.113,-43.148) 1(-22.113,-43.123) 1(-22.113,-43.097) 1(-22.113,-43.072) 1(-22.113,-43.047) 1(-22.113,-43.021) 1(-22.113,-42.996) 1(-22.113,-42.97) 1(-22.113,-42.945) 1(-22.113,-42.92) 1(-22.113,-42.894) 1(-22.113,-42.869) 1(-22.113,-42.843) 1(-22.113,-42.818) 1(-22.062,-46.298) 1(-22.012,-46.272) 1(-21.961,-46.247) 1(-21.961,-46.222) 1(-21.961,-46.196) 1(-21.961,-46.171) 1(-21.961,-46.145) 1(-21.961,-46.12) 1(-21.961,-46.095) 1(-21.961,-46.069) 1(-21.961,-46.044) 1(-21.961,-46.018) 1(-21.961,-45.993) 1(-21.961,-45.968) 1(-21.961,-45.942) 1(-21.961,-45.917) 1(-21.961,-45.891) 1(-21.961,-45.866) 1(-21.961,-45.841) 1(-21.961,-45.815) 1(-21.961,-45.79) 1(-21.961,-45.764) 1(-21.961,-45.739) 1(-21.961,-45.714) 1(-21.961,-45.688) 1(-21.961,-45.663) 1(-21.961,-45.637) 1(-21.961,-45.612) 1(-21.961,-45.587) 1(-21.961,-45.561) 1(-21.961,-45.536) 1(-21.961,-45.51) 1(-21.961,-45.485) 1(-21.961,-45.46) 1(-21.961,-45.434) 1(-21.961,-45.409) 1(-21.961,-45.383) 1(-21.961,-45.358) 1(-21.961,-45.333) 1(-21.961,-45.307) 1(-21.961,-45.282) 1(-21.961,-45.256) 1(-21.961,-45.231) 1(-21.961,-45.206) 1(-21.961,-45.18) 1(-21.961,-45.155) 1(-21.961,-45.129) 1(-21.961,-45.104) 1(-21.961,-45.079) 1(-21.961,-45.053) 1(-21.961,-45.028) 1(-21.961,-45.002) 1(-21.961,-44.977) 1(-21.961,-44.952) 1(-21.961,-44.926) 1(-21.961,-44.901) 1(-21.961,-44.875) 1(-21.961,-44.85) 1(-21.961,-44.825) 1(-21.961,-44.799) 1(-21.961,-44.774) 1(-21.961,-44.748) 1(-21.961,-44.723) 1(-21.961,-44.698) 1(-21.961,-44.672) 1(-21.961,-44.647) 1(-21.961,-44.621) 1(-21.961,-44.596) 1(-21.961,-44.571) 1(-21.961,-44.545) 1(-21.961,-44.52) 1(-21.961,-44.494) 1(-21.961,-44.469) 1(-21.961,-44.444) 1(-21.961,-44.418) 1(-21.961,-44.393) 1(-21.961,-44.367) 1(-21.504,-45.942) 1(-21.504,-45.917) 1(-21.504,-45.891) 1(-21.504,-45.866) 1(-21.504,-45.841) 1(-21.504,-45.815) 1(-21.504,-45.79) 1(-21.504,-45.764) 1(-21.504,-45.739) 1(-21.504,-45.714) 1(-21.504,-45.688) 1(-21.504,-45.663) 1(-21.504,-45.637) 1(-21.504,-45.612) 1(-21.504,-45.587) 1(-21.504,-45.561) 1(-21.504,-45.536) 1(-21.478,-46.044) 1(-21.478,-46.018) 1(-21.478,-45.993) 1(-21.478,-45.968) 1(-21.478,-45.51) 1(-21.478,-45.485) 1(-21.478,-45.46) 1(-21.453,-46.095) 1(-21.453,-46.069) 1(-21.453,-45.434) 1(-21.453,-45.409) 1(-21.453,-45.383) 1(-21.427,-46.145) 1(-21.427,-46.12) 1(-21.427,-45.358) 1(-21.427,-45.333) 1(-21.402,-46.196) 1(-21.402,-46.171) 1(-21.402,-45.307) 1(-21.402,-45.282) 1(-21.377,-46.222) 1(-21.377,-45.256) 1(-21.351,-46.272) 1(-21.351,-46.247) 1(-21.351,-45.231) 1(-21.351,-45.206) 1(-21.326,-46.298) 1(-21.326,-45.18) 1(-21.3,-46.323) 1(-21.3,-45.155) 1(-21.275,-46.349) 1(-21.275,-45.129) 1(-21.25,-46.374) 1(-21.25,-45.104) 1(-21.25,-44.545) 1(-21.25,-44.52) 1(-21.25,-44.494) 1(-21.25,-44.469) 1(-21.25,-44.444) 1(-21.25,-44.418) 1(-21.25,-44.393) 1(-21.25,-44.367) 1(-21.25,-44.342) 1(-21.25,-44.317) 1(-21.25,-44.291) 1(-21.25,-44.266) 1(-21.25,-44.24) 1(-21.25,-44.215) 1(-21.25,-44.19) 1(-21.25,-44.164) 1(-21.25,-44.139) 1(-21.25,-44.113) 1(-21.25,-44.088) 1(-21.25,-44.063) 1(-21.25,-44.037) 1(-21.25,-44.012) 1(-21.25,-43.986) 1(-21.25,-43.961) 1(-21.224,-45.079) 1(-21.224,-43.936) 1(-21.199,-46.399) 1(-21.173,-46.425) 1(-21.173,-45.053) 1(-21.173,-44.545) 1(-21.173,-43.91) 1(-21.148,-45.028) 1(-21.148,-44.52) 1(-21.123,-46.45) 1(-21.097,-46.476) 1(-21.097,-45.002) 1(-21.097,-44.494) 1(-21.097,-43.885) 1(-21.072,-44.469) 1(-21.046,-44.977) 1(-21.021,-46.501) 1(-21.021,-44.444) 1(-21.021,-43.859) 1(-20.996,-44.952) 1(-20.97,-44.418) 1(-20.945,-46.526) 1(-20.945,-44.926) 1(-20.945,-43.834) 1(-20.919,-44.393) 1(-20.869,-44.901) 1(-20.869,-44.367) 1(-20.843,-43.809) 1(-20.818,-46.552) 1(-20.792,-44.342) 1(-20.767,-44.875) 1(-20.742,-45.714) 1(-20.742,-45.688) 1(-20.742,-45.663) 1(-20.742,-45.637) 1(-20.742,-43.783) 1(-20.716,-45.815) 1(-20.716,-45.79) 1(-20.716,-45.764) 1(-20.716,-45.739) 1(-20.716,-45.612) 1(-20.716,-45.587) 1(-20.716,-45.561) 1(-20.716,-45.536) 1(-20.716,-44.317) 1(-20.691,-45.866) 1(-20.691,-45.841) 1(-20.691,-45.51) 1(-20.691,-45.485) 1(-20.665,-45.891) 1(-20.665,-45.46) 1(-20.665,-45.434) 1(-20.64,-45.917) 1(-20.64,-45.409) 1(-20.64,-44.85) 1(-20.615,-45.942) 1(-20.615,-45.383) 1(-20.615,-44.291) 1(-20.615,-43.758) 1(-20.589,-45.968) 1(-20.564,-45.358) 1(-20.538,-45.993) 1(-20.513,-45.333) 1(-20.462,-46.018) 1(-20.462,-45.307) 1(-20.462,-44.825) 1(-20.462,-44.266) 1(-20.437,-46.552) 1(-20.437,-43.732) 1(-20.361,-45.282) 1(-20.31,-46.526) 1(-20.284,-44.799) 1(-20.259,-46.018) 1(-20.234,-46.501) 1(-20.183,-46.476) 1(-20.183,-45.256) 1(-20.157,-45.993) 1(-20.157,-44.266) 1(-20.132,-46.45) 1(-20.107,-45.968) 1(-20.107,-44.774) 1(-20.081,-46.425) 1(-20.081,-45.942) 1(-20.081,-44.291) 1(-20.056,-46.399) 1(-20.03,-46.374) 1(-20.03,-45.917) 1(-20.005,-45.891) 1(-20.005,-45.231) 1(-20.005,-44.317) 1(-19.98,-46.349) 1(-19.98,-45.866) 1(-19.98,-44.342) 1(-19.954,-46.323) 1(-19.954,-45.841) 1(-19.954,-44.367) 1(-19.954,-43.732) 1(-19.929,-46.298) 1(-19.929,-45.815) 1(-19.929,-45.79) 1(-19.929,-44.393) 1(-19.903,-46.272) 1(-19.903,-45.764) 1(-19.903,-44.748) 1(-19.903,-44.418) 1(-19.878,-46.247) 1(-19.878,-46.222) 1(-19.878,-45.739) 1(-19.878,-45.714) 1(-19.878,-45.688) 1(-19.878,-44.469) 1(-19.878,-44.444) 1(-19.853,-46.196) 1(-19.853,-45.663) 1(-19.853,-45.637) 1(-19.853,-44.52) 1(-19.853,-44.494) 1(-19.827,-46.501) 1(-19.827,-46.476) 1(-19.827,-46.45) 1(-19.827,-46.425) 1(-19.827,-46.399) 1(-19.827,-46.374) 1(-19.827,-46.349) 1(-19.827,-46.323) 1(-19.827,-46.298) 1(-19.827,-46.272) 1(-19.827,-46.247) 1(-19.827,-46.222) 1(-19.827,-46.196) 1(-19.827,-45.612) 1(-19.827,-45.587) 1(-19.827,-45.561) 1(-19.827,-45.536) 1(-19.827,-45.51) 1(-19.827,-45.485) 1(-19.827,-44.647) 1(-19.827,-44.621) 1(-19.827,-44.596) 1(-19.827,-44.571) 1(-19.827,-44.545) 1(-19.802,-45.46) 1(-19.802,-45.434) 1(-19.802,-45.409) 1(-19.802,-45.383) 1(-19.802,-45.358) 1(-19.802,-45.333) 1(-19.802,-45.307) 1(-19.802,-45.282) 1(-19.802,-45.256) 1(-19.802,-45.231) 1(-19.802,-44.723) 1(-19.802,-44.698) 1(-19.802,-44.672) 1(-19.802,-43.758) 1(-19.7,-43.783) 1(-19.624,-43.809) 1(-19.548,-43.834) 1(-19.497,-43.859) 1(-19.472,-43.885) 1(-19.421,-43.91) 1(-19.395,-43.936) 1(-19.345,-43.961) 1(-19.319,-43.986) 1(-19.294,-44.012) 1(-19.268,-44.037) 1(-19.243,-44.088) 1(-19.243,-44.063) 1(-19.218,-44.113) 1(-19.192,-44.164) 1(-19.192,-44.139) 1(-19.167,-44.19) 1(-19.141,-44.24) 1(-19.141,-44.215) 1(-19.116,-44.317) 1(-19.116,-44.291) 1(-19.116,-44.266) 1(-19.091,-44.393) 1(-19.091,-44.367) 1(-19.091,-44.342) 1(-19.065,-44.494) 1(-19.065,-44.469) 1(-19.065,-44.444) 1(-19.065,-44.418) 1(-19.04,-44.647) 1(-19.04,-44.621) 1(-19.04,-44.596) 1(-19.04,-44.571) 1(-19.04,-44.545) 1(-19.04,-44.52) 1(-19.014,-46.501) 1(-19.014,-46.476) 1(-19.014,-46.45) 1(-19.014,-46.425) 1(-19.014,-46.399) 1(-19.014,-46.374) 1(-19.014,-46.349) 1(-19.014,-46.323) 1(-19.014,-46.298) 1(-19.014,-46.272) 1(-19.014,-46.247) 1(-19.014,-46.222) 1(-19.014,-46.196) 1(-19.014,-46.171) 1(-19.014,-46.145) 1(-19.014,-46.12) 1(-19.014,-46.095) 1(-19.014,-46.069) 1(-19.014,-46.044) 1(-19.014,-46.018) 1(-19.014,-45.993) 1(-19.014,-45.968) 1(-19.014,-45.942) 1(-19.014,-45.917) 1(-19.014,-45.891) 1(-19.014,-45.866) 1(-19.014,-45.841) 1(-19.014,-45.815) 1(-19.014,-45.79) 1(-19.014,-45.764) 1(-19.014,-45.739) 1(-19.014,-45.714) 1(-19.014,-45.688) 1(-19.014,-45.663) 1(-19.014,-45.637) 1(-19.014,-45.612) 1(-19.014,-45.587) 1(-19.014,-45.561) 1(-19.014,-45.536) 1(-19.014,-45.51) 1(-19.014,-45.485) 1(-19.014,-45.46) 1(-19.014,-45.434) 1(-19.014,-45.409) 1(-19.014,-45.383) 1(-19.014,-45.358) 1(-19.014,-45.333) 1(-19.014,-45.307) 1(-19.014,-45.282) 1(-19.014,-45.256) 1(-19.014,-45.231) 1(-19.014,-45.206) 1(-19.014,-45.18) 1(-19.014,-45.155) 1(-19.014,-45.129) 1(-19.014,-45.104) 1(-19.014,-45.079) 1(-19.014,-45.053) 1(-19.014,-45.028) 1(-19.014,-45.002) 1(-19.014,-44.977) 1(-19.014,-44.952) 1(-19.014,-44.926) 1(-19.014,-44.901) 1(-19.014,-44.875) 1(-19.014,-44.85) 1(-19.014,-44.825) 1(-19.014,-44.799) 1(-19.014,-44.774) 1(-19.014,-44.748) 1(-19.014,-44.723) 1(-19.014,-44.698) 1(-19.014,-44.672) 1(-18.608,-44.367) 1(-18.608,-44.342) 1(-18.608,-44.317) 1(-18.608,-44.291) 1(-18.608,-44.266) 1(-18.608,-44.24) 1(-18.608,-44.215) 1(-18.608,-44.19) 1(-18.608,-44.164) 1(-18.608,-44.139) 1(-18.608,-44.113) 1(-18.608,-44.088) 1(-18.608,-44.063) 1(-18.608,-44.037) 1(-18.608,-44.012) 1(-18.608,-43.986) 1(-18.608,-43.961) 1(-18.608,-43.936) 1(-18.608,-43.91) 1(-18.608,-43.885) 1(-18.608,-43.859) 1(-18.608,-43.834) 1(-18.608,-43.809) 1(-18.608,-43.783) 1(-18.176,-45.764) 1(-18.176,-45.739) 1(-18.176,-45.714) 1(-18.176,-45.688) 1(-18.176,-45.663) 1(-18.176,-45.637) 1(-18.176,-45.612) 1(-18.176,-45.587) 1(-18.176,-45.561) 1(-18.176,-45.536) 1(-18.176,-45.51) 1(-18.176,-45.485) 1(-18.176,-45.46) 1(-18.176,-45.434) 1(-18.176,-45.409) 1(-18.176,-45.383) 1(-18.176,-45.358) 1(-18.176,-45.333) 1(-18.176,-45.307) 1(-18.176,-45.282) 1(-18.176,-45.256) 1(-18.176,-45.231) 1(-18.176,-45.206) 1(-18.176,-45.18) 1(-18.176,-45.155) 1(-18.176,-45.129) 1(-18.176,-45.104) 1(-18.176,-45.079) 1(-18.176,-45.053) 1(-18.176,-45.028) 1(-18.176,-45.002) 1(-18.176,-44.977) 1(-18.176,-44.952) 1(-18.176,-44.926) 1(-18.176,-44.901) 1(-18.176,-44.875) 1(-18.176,-44.85) 1(-18.176,-44.825) 1(-18.176,-44.799) 1(-18.176,-44.774) 1(-18.176,-44.748) 1(-18.176,-44.723) 1(-18.176,-44.698) 1(-18.176,-44.672) 1(-18.176,-44.647) 1(-18.176,-44.621) 1(-18.176,-44.596) 1(-18.176,-44.571) 1(-18.176,-44.545) 1(-18.176,-44.52) 1(-18.176,-44.494) 1(-18.176,-44.469) 1(-18.176,-44.444) 1(-18.176,-44.418) 1(-18.176,-44.393) 1(-18.176,-43.758) 1(-18.176,-43.732) 1(-18.176,-43.707) 1(-18.176,-43.682) 1(-18.176,-43.656) 1(-18.176,-43.631) 1(-18.176,-43.605) 1(-18.176,-43.58) 1(-18.176,-43.555) 1(-18.176,-43.529) 1(-18.176,-43.504) 1(-18.176,-43.478) 1(-18.176,-43.453) 1(-18.176,-43.428) 1(-18.176,-43.402) 1(-18.176,-43.377) 1(-18.176,-43.351) 1(-18.176,-43.326) 1(-18.176,-43.301) 1(-18.176,-43.275) 1(-18.176,-43.25) 1(-18.176,-43.224) 1(-18.176,-43.199) 1(-18.176,-43.174) 1(-18.151,-45.942) 1(-18.151,-45.917) 1(-18.151,-45.891) 1(-18.151,-45.866) 1(-18.151,-45.841) 1(-18.151,-45.815) 1(-18.151,-45.79) 1(-18.125,-46.044) 1(-18.125,-46.018) 1(-18.125,-45.993) 1(-18.125,-45.968) 1(-18.125,-43.148) 1(-18.1,-46.12) 1(-18.1,-46.095) 1(-18.1,-46.069) 1(-18.075,-46.171) 1(-18.075,-46.145) 1(-18.049,-46.222) 1(-18.049,-46.196) 1(-18.024,-46.247) 1(-18.024,-43.123) 1(-17.998,-46.272) 1(-17.973,-46.323) 1(-17.973,-46.298) 1(-17.948,-46.349) 1(-17.948,-43.097) 1(-17.922,-46.374) 1(-17.871,-46.399) 1(-17.846,-46.425) 1(-17.846,-43.072) 1(-17.795,-46.45) 1(-17.77,-43.047) 1(-17.744,-46.476) 1(-17.694,-46.501) 1(-17.668,-43.021) 1(-17.617,-46.526) 1(-17.592,-42.996) 1(-17.49,-46.552) 1(-17.49,-42.97) 1(-17.414,-42.945) 1(-17.338,-45.637) 1(-17.338,-45.612) 1(-17.338,-45.587) 1(-17.338,-45.561) 1(-17.338,-45.536) 1(-17.338,-45.51) 1(-17.338,-45.485) 1(-17.338,-45.46) 1(-17.338,-45.434) 1(-17.338,-45.409) 1(-17.338,-45.383) 1(-17.338,-45.358) 1(-17.338,-45.333) 1(-17.338,-45.307) 1(-17.338,-45.282) 1(-17.338,-45.256) 1(-17.338,-45.231) 1(-17.338,-45.206) 1(-17.338,-45.18) 1(-17.338,-45.155) 1(-17.338,-45.129) 1(-17.338,-45.104) 1(-17.338,-45.079) 1(-17.338,-45.053) 1(-17.338,-45.028) 1(-17.338,-45.002) 1(-17.338,-44.977) 1(-17.338,-44.952) 1(-17.338,-44.926) 1(-17.338,-44.901) 1(-17.338,-44.875) 1(-17.338,-44.85) 1(-17.338,-44.825) 1(-17.338,-44.799) 1(-17.338,-44.774) 1(-17.338,-44.748) 1(-17.338,-44.723) 1(-17.338,-44.698) 1(-17.338,-44.672) 1(-17.338,-44.647) 1(-17.338,-44.621) 1(-17.338,-44.596) 1(-17.338,-44.571) 1(-17.338,-44.545) 1(-17.338,-44.52) 1(-17.338,-44.494) 1(-17.338,-44.469) 1(-17.338,-44.444) 1(-17.338,-44.418) 1(-17.338,-44.393) 1(-17.338,-43.758) 1(-17.338,-43.732) 1(-17.338,-43.707) 1(-17.338,-43.682) 1(-17.338,-43.656) 1(-17.338,-43.631) 1(-17.338,-43.605) 1(-17.338,-43.58) 1(-17.338,-43.555) 1(-17.338,-43.529) 1(-17.338,-43.504) 1(-17.338,-43.478) 1(-17.338,-43.453) 1(-17.338,-43.428) 1(-17.338,-43.402) 1(-17.338,-43.377) 1(-17.338,-43.351) 1(-17.338,-43.326) 1(-17.338,-43.301) 1(-17.338,-43.275) 1(-17.338,-43.25) 1(-17.338,-43.224) 1(-17.338,-43.199) 1(-17.338,-43.174) 1(-17.338,-43.148) 1(-17.338,-43.123) 1(-17.338,-43.097) 1(-17.338,-43.072) 1(-17.338,-43.047) 1(-17.338,-43.021) 1(-17.338,-42.996) 1(-17.338,-42.97) 1(-17.338,-42.945) 1(-17.313,-45.739) 1(-17.313,-45.714) 1(-17.313,-45.688) 1(-17.313,-45.663) 1(-17.287,-45.79) 1(-17.287,-45.764) 1(-17.262,-45.841) 1(-17.262,-45.815) 1(-17.236,-45.866) 1(-17.211,-45.891) 1(-17.16,-45.917) 1(-17.084,-45.942) 1(-17.008,-46.552) 1(-16.906,-45.942) 1(-16.881,-46.526) 1(-16.83,-45.917) 1(-16.779,-46.501) 1(-16.779,-45.891) 1(-16.728,-46.476) 1(-16.703,-46.45) 1(-16.703,-46.425) 1(-16.703,-46.399) 1(-16.703,-46.374) 1(-16.703,-46.349) 1(-16.703,-46.323) 1(-16.703,-46.298) 1(-16.703,-46.272) 1(-16.703,-46.247) 1(-16.703,-46.222) 1(-16.703,-46.196) 1(-16.703,-46.171) 1(-16.703,-46.145) 1(-16.703,-46.12) 1(-16.703,-46.095) 1(-16.703,-46.069) 1(-16.703,-46.044) 1(-16.703,-46.018) 1(-16.703,-45.993) 1(-16.703,-45.968) 1(-16.703,-45.942) 1(-16.703,-45.917) 1(-16.703,-45.891) 1(-16.703,-44.367) 1(-16.703,-44.342) 1(-16.703,-44.317) 1(-16.703,-44.291) 1(-16.703,-44.266) 1(-16.703,-44.24) 1(-16.703,-44.215) 1(-16.703,-44.19) 1(-16.703,-44.164) 1(-16.703,-44.139) 1(-16.703,-44.113) 1(-16.703,-44.088) 1(-16.703,-44.063) 1(-16.703,-44.037) 1(-16.703,-44.012) 1(-16.703,-43.986) 1(-16.703,-43.961) 1(-16.703,-43.936) 1(-16.703,-43.91) 1(-16.703,-43.885) 1(-16.703,-43.859) 1(-16.703,-43.834) 1(-16.703,-43.809) 1(-16.703,-43.783) 1(-16.424,-45.383) 1(-16.424,-45.358) 1(-16.424,-45.333) 1(-16.424,-45.307) 1(-16.424,-45.282) 1(-16.424,-45.256) 1(-16.424,-45.231) 1(-16.424,-45.206) 1(-16.424,-45.18) 1(-16.424,-45.155) 1(-16.424,-45.129) 1(-16.424,-45.104) 1(-16.424,-45.079) 1(-16.424,-45.053) 1(-16.424,-45.028) 1(-16.424,-45.002) 1(-16.398,-45.561) 1(-16.398,-45.536) 1(-16.398,-45.51) 1(-16.398,-45.485) 1(-16.398,-45.46) 1(-16.398,-45.434) 1(-16.398,-45.409) 1(-16.398,-44.977) 1(-16.398,-44.952) 1(-16.398,-44.926) 1(-16.398,-44.901) 1(-16.398,-44.875) 1(-16.398,-44.85) 1(-16.398,-44.825) 1(-16.373,-45.663) 1(-16.373,-45.637) 1(-16.373,-45.612) 1(-16.373,-45.587) 1(-16.373,-44.799) 1(-16.373,-44.774) 1(-16.373,-44.748) 1(-16.373,-44.723) 1(-16.347,-45.739) 1(-16.347,-45.714) 1(-16.347,-45.688) 1(-16.347,-44.698) 1(-16.347,-44.672) 1(-16.347,-44.647)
